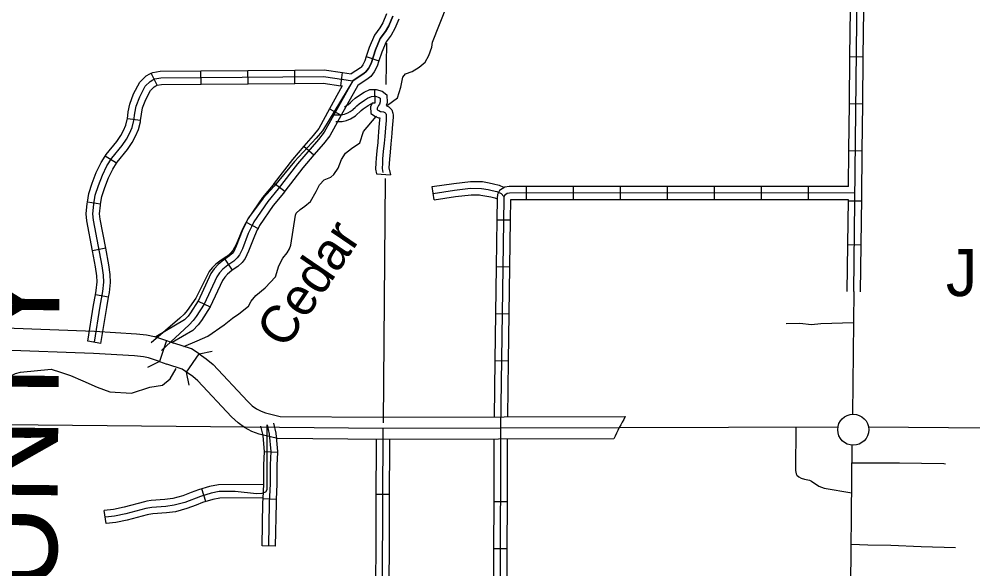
# Model space of a CAD drawing. Extents: x 1373862 to 1376999, y 1168398 to 1170455.
# Drawn here: x 1375582.6 to 1375797.1, y 1168974.9 to 1169098.5 of the extents above; entities that cross this region are included whole.
import ezdxf

# ---------------------------------------------------------------- set-up
doc = ezdxf.new("R2010")
doc.units = 0
for name, color, linetype in [('Level 10', 7, 'Continuous'), ('Level 24', 7, 'Continuous'), ('Level 32', 7, 'Continuous'), ('Level 35', 7, 'Continuous'), ('Level 37', 7, 'Continuous'), ('Level 45', 7, 'Continuous'), ('Level 5', 7, 'Continuous'), ('R_Draft', 7, 'Continuous')]:
    doc.layers.add(name, color=color, linetype=linetype)

msp = doc.modelspace()

# ---------------------------------------------------------------- linework, layer by layer
at = {"layer": 'Level 10'}
for p, q in [((1375615.72, 1169026.21), (1375614.14, 1169021.46)), ((1375620.24, 1169019.11), (1375623.06, 1169023.24))]:
    msp.add_line(p, q, dxfattribs=at)
for points in [[(1375575.37, 1169030.16), (1375578.04, 1169029.33), (1375579.42, 1169029.05), (1375599.53, 1169028.31), (1375608.93, 1169027.73), (1375611.24, 1169027.49), (1375612.98, 1169027.15), (1375615.72, 1169026.21)], [(1375614.14, 1169021.46), (1375611.68, 1169022.31), (1375610.51, 1169022.54), (1375608.53, 1169022.74), (1375599.28, 1169023.32), (1375578.83, 1169024.07), (1375576.8, 1169024.48), (1375573.88, 1169025.39)], [(1375615.72, 1169026.21), (1375617.39, 1169025.63)], [(1375623.06, 1169023.24), (1375621.32, 1169024.31), (1375617.39, 1169025.63)], [(1375623.06, 1169023.24), (1375624.66, 1169022.09), (1375626.18, 1169020.84), (1375633.91, 1169012.58), (1375634.98, 1169011.56), (1375635.92, 1169010.89), (1375636.99, 1169010.3), (1375637.98, 1169009.95), (1375641.3, 1169009.17), (1375664.44, 1169008.95), (1375718.89, 1169009.1)], [(1375614.14, 1169021.46), (1375615.75, 1169020.91)], [(1375620.24, 1169019.11), (1375619.2, 1169019.75), (1375615.75, 1169020.91)], [(1375716.29, 1169004.09), (1375664.43, 1169003.95), (1375640.69, 1169004.17), (1375636.55, 1169005.15), (1375634.93, 1169005.73), (1375633.27, 1169006.65), (1375631.79, 1169007.69), (1375630.36, 1169009.06), (1375622.75, 1169017.18), (1375621.61, 1169018.12), (1375620.24, 1169019.11)], [(1375766.7, 1169006.73), (1375717.51, 1169006.6)], [(1375810.66, 1168942.85), (1375802.81, 1168949.14), (1375798.84, 1168952.2), (1375796.61, 1168953.74), (1375794.39, 1168954.87), (1375775.91, 1168959.64), (1375772.5, 1168960.73), (1375771.74, 1168961.21), (1375770.37, 1168962.36), (1375769.5, 1168963.6), (1375769.9, 1169002.68)]]:
    msp.add_lwpolyline(points, dxfattribs=at)
msp.add_arc((1375767.97, 1168980.4), 56.86, 149.6783, 155.3676, dxfattribs=at)
at = {"layer": 'Level 24'}
msp.add_circle((1375770.15, 1169006.17), 3.5, dxfattribs=at)
at = {"layer": 'Level 32'}
for p, q in [((1375660.64, 1169090.04), (1375663.48, 1169089.09)), ((1375769.4, 1169090.02), (1375772.4, 1169089.98)), ((1375613.6, 1169083.58), (1375612.29, 1169086.28)), ((1375623.48, 1169083.82), (1375623.45, 1169086.82)), ((1375634.04, 1169083.91), (1375634.01, 1169086.91)), ((1375644.6, 1169084.01), (1375644.57, 1169087.01)), ((1375654.89, 1169083.49), (1375655.32, 1169086.46)), ((1375769.28, 1169079.46), (1375772.28, 1169079.42)), ((1375652.37, 1169078.29), (1375655, 1169076.84)), ((1375609.89, 1169075.7), (1375606.92, 1169076.06)), ((1375646.6, 1169069.88), (1375648.87, 1169067.92)), ((1375769.17, 1169068.9), (1375772.17, 1169068.86)), ((1375604.46, 1169066.07), (1375601.92, 1169067.66)), ((1375639.95, 1169061.57), (1375642.34, 1169059.75)), ((1375696.61, 1169060.83), (1375696.61, 1169057.83)), ((1375707.17, 1169060.83), (1375707.17, 1169057.83)), ((1375717.73, 1169060.83), (1375717.73, 1169057.83)), ((1375728.29, 1169060.83), (1375728.29, 1169057.83)), ((1375738.85, 1169060.83), (1375738.85, 1169057.83)), ((1375749.41, 1169060.84), (1375749.41, 1169057.84)), ((1375759.97, 1169060.84), (1375759.97, 1169057.84)), ((1375769.11, 1169057.62), (1375772.11, 1169057.59)), ((1375600.9, 1169056.86), (1375597.93, 1169057.33)), ((1375690, 1169053.37), (1375693, 1169053.33)), ((1375633.65, 1169052.82), (1375636.29, 1169051.41)), ((1375602.04, 1169046.95), (1375599.09, 1169046.39)), ((1375768.93, 1169047.78), (1375771.93, 1169047.75)), ((1375628.84, 1169044.51), (1375630.51, 1169042.02)), ((1375689.85, 1169042.82), (1375692.85, 1169042.77)), ((1375602.69, 1169035.96), (1375599.74, 1169036.5)), ((1375622.84, 1169035.06), (1375625.56, 1169033.8)), ((1375689.7, 1169032.26), (1375692.7, 1169032.21)), ((1375600.98, 1169025.57), (1375598.02, 1169026.05)), ((1375689.55, 1169021.7), (1375692.55, 1169021.66)), ((1375640.76, 1169001.03), (1375637.76, 1169001.21)), ((1375640.45, 1168990.5), (1375637.45, 1168990.63)), ((1375689.3, 1168990), (1375692.3, 1168990)), ((1375640.24, 1168979.98), (1375637.24, 1168980.04)), ((1375689.28, 1168979.44), (1375692.28, 1168979.44))]:
    msp.add_line(p, q, dxfattribs=at)
for points in [[(1375770.29, 1169037.2), (1375771.11, 1169111.53), (1375771.83, 1169217.93)], [(1375769.4, 1169090.02), (1375769.52, 1169100.58)], [(1375772.4, 1169089.98), (1375772.52, 1169100.54)], [(1375666.59, 1169099.11), (1375665.69, 1169096.98), (1375664.93, 1169095.65), (1375663.78, 1169094.08), (1375662.72, 1169091.54), (1375661.7, 1169088.49), (1375661.11, 1169087.36), (1375660.55, 1169086.58), (1375660.19, 1169086.29), (1375657.58, 1169084.61)], [(1375665.19, 1169099.63), (1375664.34, 1169097.64), (1375663.67, 1169096.46), (1375662.47, 1169094.82), (1375661.32, 1169092.07), (1375660.64, 1169090.04)], [(1375667.95, 1169098.46), (1375667.03, 1169096.31), (1375666.2, 1169094.83), (1375665.1, 1169093.33), (1375664.13, 1169091.02), (1375663.48, 1169089.09)], [(1375660.64, 1169090.04), (1375660.32, 1169089.08), (1375659.83, 1169088.15), (1375659.45, 1169087.62), (1375659.32, 1169087.52), (1375657.24, 1169086.18)], [(1375769.28, 1169079.46), (1375769.4, 1169090.02)], [(1375772.28, 1169079.42), (1375772.4, 1169089.98)], [(1375663.48, 1169089.09), (1375663.09, 1169087.9), (1375662.39, 1169086.58), (1375661.65, 1169085.53), (1375661.07, 1169085.07), (1375658.71, 1169083.55)], [(1375599.5, 1169025.81), (1375600.78, 1169033.9), (1375601.4, 1169037.23), (1375601.63, 1169039.34), (1375601.56, 1169040.9), (1375601.26, 1169043), (1375599.3, 1169053.29), (1375599.17, 1169054.71), (1375599.38, 1169056.85), (1375599.7, 1169058.9), (1375600.41, 1169061.07), (1375601.29, 1169063.38), (1375602.32, 1169065.47), (1375603.39, 1169067.18), (1375605.73, 1169070.05), (1375606.72, 1169071.48), (1375607.42, 1169072.76), (1375608.01, 1169074.11), (1375608.38, 1169075.64), (1375608.58, 1169077.34), (1375608.89, 1169078.91), (1375609.68, 1169081.02), (1375610.9, 1169083.35), (1375612.06, 1169084.46), (1375612.66, 1169084.79), (1375613.12, 1169085.01), (1375614.42, 1169085.24), (1375651.05, 1169085.56), (1375657.58, 1169084.61), (1375651.2, 1169073.06), (1375649.87, 1169071.37), (1375645.18, 1169065.94), (1375640.85, 1169060.28), (1375638.47, 1169057.43), (1375635.38, 1169052.88), (1375634.79, 1169051.77), (1375634.1, 1169050.29), (1375632.78, 1169046.85), (1375632.13, 1169045.46), (1375631.61, 1169044.78), (1375630.84, 1169044.05), (1375629.54, 1169043.18), (1375628.38, 1169042.23), (1375627.63, 1169041.4), (1375627, 1169040.49), (1375624.18, 1169034.38), (1375622.37, 1169031.58), (1375621.72, 1169030.71), (1375620.8, 1169029.76), (1375614.55, 1169023.97)], [(1375606.92, 1169076.06), (1375607.1, 1169077.58), (1375607.45, 1169079.32), (1375608.31, 1169081.63), (1375609.69, 1169084.26), (1375611.16, 1169085.68), (1375611.97, 1169086.12), (1375612.29, 1169086.28)], [(1375612.29, 1169086.28), (1375612.65, 1169086.45), (1375614.28, 1169086.74), (1375623.45, 1169086.82)], [(1375623.45, 1169086.82), (1375634.01, 1169086.91)], [(1375634.01, 1169086.91), (1375644.57, 1169087.01)], [(1375644.57, 1169087.01), (1375651.15, 1169087.06), (1375655.32, 1169086.46)], [(1375655.32, 1169086.46), (1375657.24, 1169086.18)], [(1375609.89, 1169075.7), (1375610.07, 1169077.11), (1375610.34, 1169078.5), (1375611.05, 1169080.41), (1375612.12, 1169082.44), (1375612.95, 1169083.24), (1375613.34, 1169083.45), (1375613.6, 1169083.58)], [(1375613.58, 1169083.57), (1375614.55, 1169083.74), (1375623.48, 1169083.82)], [(1375623.48, 1169083.82), (1375634.04, 1169083.91)], [(1375634.04, 1169083.91), (1375644.6, 1169084.01)], [(1375644.6, 1169084.01), (1375650.94, 1169084.06), (1375654.89, 1169083.49)], [(1375654.89, 1169083.49), (1375655.22, 1169083.44), (1375652.37, 1169078.29)], [(1375658.71, 1169083.55), (1375655, 1169076.84)], [(1375769.17, 1169068.9), (1375769.28, 1169079.46)], [(1375772.17, 1169068.86), (1375772.28, 1169079.42)], [(1375652.37, 1169078.29), (1375649.94, 1169073.89), (1375648.71, 1169072.32), (1375646.6, 1169069.88)], [(1375655, 1169076.84), (1375652.45, 1169072.23), (1375651.02, 1169070.41), (1375648.87, 1169067.92)], [(1375601.92, 1169067.66), (1375602.17, 1169068.06), (1375604.53, 1169070.95), (1375605.44, 1169072.26), (1375606.07, 1169073.42), (1375606.58, 1169074.59), (1375606.9, 1169075.91), (1375606.92, 1169076.06)], [(1375604.46, 1169066.07), (1375604.61, 1169066.31), (1375606.93, 1169069.14), (1375608, 1169070.69), (1375608.76, 1169072.11), (1375609.43, 1169073.63), (1375609.85, 1169075.37), (1375609.89, 1169075.7)], [(1375646.6, 1169069.88), (1375644.01, 1169066.89), (1375639.95, 1169061.57)], [(1375769.08, 1169060.84), (1375769.17, 1169068.9)], [(1375772.05, 1169058.31), (1375772.17, 1169068.86)], [(1375597.93, 1169057.33), (1375598.24, 1169059.25), (1375598.99, 1169061.57), (1375599.92, 1169063.98), (1375601.01, 1169066.2), (1375601.92, 1169067.66)], [(1375600.9, 1169056.86), (1375601.17, 1169058.55), (1375601.82, 1169060.57), (1375602.67, 1169062.78), (1375603.63, 1169064.74), (1375604.46, 1169066.07)], [(1375648.87, 1169067.92), (1375646.34, 1169064.99), (1375642.34, 1169059.75)], [(1375639.95, 1169061.57), (1375639.68, 1169061.21), (1375637.27, 1169058.34), (1375634.09, 1169053.66), (1375633.65, 1169052.82)], [(1375642.34, 1169059.75), (1375642.02, 1169059.34), (1375639.67, 1169056.53), (1375636.66, 1169052.1), (1375636.29, 1169051.41)], [(1375696.61, 1169060.83), (1375692.79, 1169060.82), (1375691.77, 1169060.71), (1375690.63, 1169059.9), (1375690.17, 1169059.01), (1375690.07, 1169058.22), (1375690, 1169053.37)], [(1375707.17, 1169060.83), (1375696.61, 1169060.83)], [(1375717.73, 1169060.83), (1375707.17, 1169060.83)], [(1375728.29, 1169060.83), (1375717.73, 1169060.83)], [(1375738.85, 1169060.83), (1375728.29, 1169060.83)], [(1375749.41, 1169060.84), (1375738.85, 1169060.83)], [(1375759.97, 1169060.84), (1375749.41, 1169060.84)], [(1375769.08, 1169060.84), (1375759.97, 1169060.84)], [(1375770.53, 1169059.37), (1375692.88, 1169059.35), (1375692.32, 1169059.29), (1375691.78, 1169058.9), (1375691.6, 1169058.56), (1375691.54, 1169058.12), (1375690.81, 1169006.53), (1375690.58, 1168902.11)], [(1375696.61, 1169057.83), (1375693.07, 1169057.82), (1375693, 1169053.33)], [(1375707.17, 1169057.83), (1375696.61, 1169057.83)], [(1375717.73, 1169057.83), (1375707.17, 1169057.83)], [(1375728.29, 1169057.83), (1375717.73, 1169057.83)], [(1375738.85, 1169057.83), (1375728.29, 1169057.83)], [(1375749.41, 1169057.84), (1375738.85, 1169057.83)], [(1375759.97, 1169057.84), (1375749.41, 1169057.84)], [(1375769.04, 1169057.84), (1375759.97, 1169057.84)], [(1375768.93, 1169047.78), (1375769.04, 1169057.84)], [(1375771.93, 1169047.75), (1375772.05, 1169058.31)], [(1375599.09, 1169046.39), (1375597.82, 1169053.08), (1375597.67, 1169054.71), (1375597.89, 1169057.04), (1375597.93, 1169057.33)], [(1375602.04, 1169046.95), (1375600.79, 1169053.49), (1375600.68, 1169054.7), (1375600.87, 1169056.66), (1375600.9, 1169056.86)], [(1375690, 1169053.37), (1375689.85, 1169042.82)], [(1375693, 1169053.33), (1375692.85, 1169042.77)], [(1375633.65, 1169052.82), (1375633.44, 1169052.44), (1375632.71, 1169050.87), (1375631.4, 1169047.44), (1375630.84, 1169046.24), (1375630.49, 1169045.78), (1375629.9, 1169045.23), (1375628.84, 1169044.51)], [(1375636.29, 1169051.41), (1375636.13, 1169051.1), (1375635.48, 1169049.7), (1375634.16, 1169046.26), (1375633.42, 1169044.68), (1375632.73, 1169043.77), (1375631.77, 1169042.87), (1375630.51, 1169042.02)], [(1375602.69, 1169035.96), (1375602.89, 1169037.01), (1375603.13, 1169039.29), (1375603.05, 1169041.04), (1375602.74, 1169043.25), (1375602.04, 1169046.95)], [(1375768.81, 1169037.24), (1375768.93, 1169047.78)], [(1375771.81, 1169037.12), (1375771.93, 1169047.75)], [(1375599.74, 1169036.5), (1375599.92, 1169037.45), (1375600.12, 1169039.38), (1375600.06, 1169040.76), (1375599.78, 1169042.76), (1375599.09, 1169046.39)], [(1375628.84, 1169044.51), (1375628.64, 1169044.38), (1375627.35, 1169043.32), (1375626.46, 1169042.34), (1375625.69, 1169041.24), (1375622.84, 1169035.06)], [(1375689.85, 1169042.82), (1375689.7, 1169032.26)], [(1375692.85, 1169042.77), (1375692.7, 1169032.21)], [(1375630.51, 1169042.02), (1375630.44, 1169041.97), (1375629.42, 1169041.14), (1375628.8, 1169040.46), (1375628.3, 1169039.74), (1375625.56, 1169033.8)], [(1375598.02, 1169026.05), (1375599.31, 1169034.15), (1375599.74, 1169036.5)], [(1375770.29, 1169037.2), (1375769.98, 1169009.66)], [(1375600.98, 1169025.57), (1375602.26, 1169033.65), (1375602.69, 1169035.96)], [(1375622.86, 1169035.1), (1375621.14, 1169032.44), (1375620.58, 1169031.69), (1375619.75, 1169030.84), (1375613.29, 1169027.05)], [(1375625.53, 1169033.76), (1375623.6, 1169030.72), (1375622.86, 1169029.74), (1375621.63, 1169028.46), (1375617.02, 1169025.76)], [(1375689.7, 1169032.26), (1375689.55, 1169021.7)], [(1375692.7, 1169032.21), (1375692.55, 1169021.66)], [(1375689.55, 1169021.7), (1375689.37, 1169009.02)], [(1375692.55, 1169021.66), (1375692.37, 1169009.03)], [(1375637.76, 1169001.21), (1375637.76, 1169001.23), (1375637.43, 1169004.9), (1375636.93, 1169006.93)], [(1375638.74, 1168980.01), (1375638.91, 1168989.75), (1375639.09, 1168993.99), (1375639.09, 1168998.24), (1375639.27, 1169001.25), (1375638.91, 1169005.15), (1375638.39, 1169007.28)], [(1375640.76, 1169001.03), (1375640.77, 1169001.28), (1375640.4, 1169005.39), (1375639.84, 1169007.64)], [(1375757.27, 1169006.71), (1375757.18, 1168997), (1375757.3, 1168996.26), (1375757.49, 1168995.92), (1375757.89, 1168995.55), (1375758.43, 1168995.25), (1375759.15, 1168995.02), (1375760.3, 1168994.8), (1375760.74, 1168994.61), (1375762.37, 1168993.48), (1375763.59, 1168993.05), (1375769.79, 1168991.97)], [(1375818.55, 1169006.35), (1375773.61, 1169006.71)], [(1375689.33, 1169004.02), (1375689.33, 1169000.56)], [(1375692.33, 1169004.03), (1375692.33, 1169000.56)], [(1375637.45, 1168990.63), (1375637.59, 1168994.02), (1375637.59, 1168998.29), (1375637.76, 1169001.21)], [(1375640.45, 1168990.5), (1375640.59, 1168993.96), (1375640.59, 1168998.2), (1375640.76, 1169001.03)], [(1375689.33, 1169000.56), (1375689.3, 1168990)], [(1375692.33, 1169000.56), (1375692.3, 1168990)], [(1375769.86, 1168998.73), (1375780.58, 1168998.73), (1375785.49, 1168998.66), (1375790.55, 1168998.58), (1375790.91, 1168998.51)], [(1375637.24, 1168980.04), (1375637.41, 1168989.79), (1375637.45, 1168990.63)], [(1375640.24, 1168979.98), (1375640.41, 1168989.7), (1375640.45, 1168990.5)], [(1375689.3, 1168990), (1375689.28, 1168979.44)], [(1375692.3, 1168990), (1375692.28, 1168979.44)], [(1375689.28, 1168979.44), (1375689.26, 1168968.88)], [(1375692.28, 1168979.44), (1375692.26, 1168968.88)]]:
    msp.add_lwpolyline(points, dxfattribs=at)
at = {"layer": 'Level 35'}
for points in [[(1375665.39, 1169079.09), (1375667.68, 1169080.79), (1375668.41, 1169083.16), (1375668.87, 1169085.41), (1375669.47, 1169086.13), (1375670.92, 1169086.7), (1375672.56, 1169087.62), (1375673.85, 1169088.79), (1375674.68, 1169090.3), (1375675.39, 1169092.17), (1375675.54, 1169093.29), (1375680.56, 1169106.04), (1375681.27, 1169106.9), (1375682.8, 1169109.38), (1375683.57, 1169113.1)], [(1375619.61, 1169024.9), (1375622.61, 1169026.11), (1375624.97, 1169027.16), (1375628.69, 1169029.72), (1375630.52, 1169031.25), (1375632.01, 1169032.21), (1375634.14, 1169033.95), (1375634.76, 1169035.08), (1375635.78, 1169036.35), (1375637.89, 1169038.04), (1375640.25, 1169040.49), (1375641, 1169043.02), (1375641.85, 1169044.76), (1375642.85, 1169045.89), (1375643.36, 1169046.8), (1375643.64, 1169047.61), (1375644.7, 1169054.4), (1375644.88, 1169054.85), (1375645.74, 1169055.69), (1375646.83, 1169056.42), (1375648.06, 1169057.47), (1375649.39, 1169059.71), (1375650.15, 1169061.22), (1375651.17, 1169062.31), (1375652.69, 1169062.91), (1375653.36, 1169063.51), (1375654.31, 1169064.94), (1375655.03, 1169066.87), (1375655.95, 1169068.31), (1375657.28, 1169069.39), (1375659.18, 1169070.68), (1375660.04, 1169073.18), (1375662.84, 1169076.57), (1375662.95, 1169076.67)], [(1375576.56, 1169012.93), (1375579.62, 1169017.34), (1375580.26, 1169018.03), (1375581.74, 1169018.8), (1375582.9, 1169019.09), (1375589.8, 1169019.78), (1375591.89, 1169019.1), (1375594.16, 1169018.34), (1375596.9, 1169017.13), (1375600.09, 1169015.76), (1375602.98, 1169014.69), (1375607.84, 1169014.39), (1375611.94, 1169015.76), (1375614.82, 1169016.21), (1375616.5, 1169017.58), (1375617.87, 1169019.95)]]:
    msp.add_lwpolyline(points, dxfattribs=at)
at = {"layer": 'Level 37'}
for points in [[(1375623.06, 1169023.24), (1375626.01, 1169023.79)], [(1375614.14, 1169021.46), (1375611.46, 1169020.12)], [(1375620.8, 1169016.16), (1375620.24, 1169019.11)]]:
    msp.add_lwpolyline(points, dxfattribs=at)
at = {"layer": 'Level 45'}
for p, q in [((1375662.62, 1169079.62), (1375662.56, 1169082.62)), ((1375662.95, 1169063.68), (1375666.06, 1169063.45)), ((1375675.87, 1169057.84), (1375675.44, 1169060.81)), ((1375624.52, 1168990), (1375623.64, 1168992.87)), ((1375662.89, 1168991.71), (1375665.89, 1168991.7)), ((1375602.12, 1168985.07), (1375601.67, 1168988.04))]:
    msp.add_line(p, q, dxfattribs=at)
for points in [[(1375657.58, 1169084.61), (1375660.19, 1169086.29), (1375660.55, 1169086.58), (1375661.11, 1169087.36), (1375661.7, 1169088.49), (1375662.72, 1169091.54), (1375663.78, 1169094.08), (1375664.93, 1169095.65), (1375665.69, 1169096.98), (1375666.59, 1169099.11)], [(1375599.5, 1169025.81), (1375600.78, 1169033.9), (1375601.4, 1169037.23), (1375601.63, 1169039.34), (1375601.56, 1169040.9), (1375601.26, 1169043), (1375599.3, 1169053.29), (1375599.17, 1169054.71), (1375599.38, 1169056.85), (1375599.7, 1169058.9), (1375600.41, 1169061.07), (1375601.29, 1169063.38), (1375602.32, 1169065.47), (1375603.39, 1169067.18), (1375605.73, 1169070.05), (1375606.72, 1169071.48), (1375607.42, 1169072.76), (1375608.01, 1169074.11), (1375608.38, 1169075.64), (1375608.58, 1169077.34), (1375608.89, 1169078.91), (1375609.68, 1169081.02), (1375610.9, 1169083.35), (1375612.06, 1169084.46), (1375612.66, 1169084.79), (1375613.12, 1169085.01), (1375614.42, 1169085.24), (1375651.05, 1169085.56), (1375657.58, 1169084.61)], [(1375657.58, 1169084.61), (1375650.76, 1169073.31), (1375649.36, 1169071.67), (1375644.47, 1169066.43), (1375639.93, 1169060.94), (1375637.44, 1169058.19), (1375634.17, 1169053.76), (1375633.54, 1169052.68), (1375632.79, 1169051.22), (1375631.34, 1169047.83), (1375630.64, 1169046.47), (1375630.1, 1169045.81), (1375629.29, 1169045.11), (1375627.97, 1169044.29), (1375626.78, 1169043.38), (1375625.99, 1169042.58), (1375625.32, 1169041.7), (1375622.27, 1169035.7), (1375620.36, 1169032.97), (1375619.67, 1169032.13), (1375618.72, 1169031.22), (1375612.25, 1169025.67)], [(1375653.34, 1169076.93), (1375655.01, 1169076.91), (1375655.77, 1169077.11), (1375656.46, 1169077.38), (1375657.02, 1169077.71), (1375657.69, 1169078.15), (1375657.67, 1169078.19), (1375658.16, 1169078.6), (1375658.5, 1169078.97), (1375659.05, 1169079.44), (1375660.22, 1169080.26), (1375660.89, 1169080.68), (1375661.8, 1169081.08), (1375662.69, 1169081.1), (1375663.51, 1169080.87), (1375663.75, 1169080.67), (1375663.79, 1169079.85), (1375663.62, 1169079.31), (1375663.37, 1169079), (1375663.07, 1169078.47), (1375663.1, 1169078.09), (1375663.43, 1169077.88), (1375663.81, 1169077.71), (1375663.97, 1169077.69), (1375664.51, 1169077.6), (1375664.8, 1169077.48), (1375665.04, 1169077.23), (1375665.12, 1169077.01), (1375665.13, 1169076.77), (1375665.14, 1169076.43), (1375665.09, 1169075.7), (1375664.94, 1169074.04), (1375664.8, 1169072.05), (1375664.67, 1169070.56), (1375664.46, 1169068.73), (1375664.31, 1169067.08), (1375664.25, 1169066.05), (1375664.21, 1169064.87), (1375664.39, 1169064.01)], [(1375655.75, 1169078.74), (1375656.21, 1169079.01), (1375656.48, 1169079.18), (1375657.1, 1169079.7), (1375657.43, 1169080.06), (1375658.11, 1169080.65), (1375659.37, 1169081.54), (1375660.18, 1169082.04), (1375661.47, 1169082.6), (1375662.56, 1169082.62)], [(1375662.56, 1169082.62), (1375662.88, 1169082.63), (1375664.22, 1169082.26), (1375665.25, 1169081.43), (1375665.33, 1169079.65), (1375665.12, 1169079), (1375665.69, 1169078.77), (1375666.38, 1169078.03), (1375666.63, 1169077.31), (1375666.66, 1169076.83), (1375666.67, 1169076.38), (1375666.61, 1169075.59), (1375666.46, 1169073.91), (1375666.39, 1169072.81)], [(1375653.77, 1169075.45), (1375655.19, 1169075.44), (1375656.22, 1169075.7), (1375657.11, 1169076.06), (1375657.12, 1169076.06), (1375658.25, 1169076.69), (1375659.52, 1169077.91), (1375659.95, 1169078.28), (1375661.03, 1169079.03), (1375661.57, 1169079.37), (1375662.12, 1169079.61), (1375662.62, 1169079.62)], [(1375662.02, 1169079.61), (1375661.58, 1169078.8), (1375661.68, 1169077.26), (1375662.71, 1169076.58), (1375663.42, 1169076.27), (1375663.65, 1169076.24), (1375663.62, 1169075.82), (1375663.47, 1169074.15), (1375663.39, 1169073.02)], [(1375663.39, 1169073.02), (1375663.33, 1169072.16), (1375663.2, 1169070.71), (1375663, 1169068.88), (1375662.84, 1169067.19), (1375662.78, 1169066.12), (1375662.73, 1169064.74), (1375662.95, 1169063.68)], [(1375666.39, 1169072.81), (1375666.32, 1169071.92), (1375666.19, 1169070.4), (1375665.98, 1169068.57), (1375665.83, 1169066.96), (1375665.78, 1169065.98), (1375665.74, 1169065), (1375666.06, 1169063.45)], [(1375675.44, 1169060.81), (1375680.31, 1169061.53), (1375684.04, 1169061.97), (1375686.17, 1169061.93)], [(1375686.17, 1169061.93), (1375686.74, 1169061.92), (1375688.3, 1169061.62), (1375689.25, 1169061.43), (1375690.5, 1169061.15), (1375691.49, 1169060.68)], [(1375675.66, 1169059.29), (1375680.51, 1169060.01), (1375684.11, 1169060.44), (1375686.58, 1169060.39), (1375688.01, 1169060.12), (1375688.93, 1169059.94), (1375690, 1169059.7), (1375690.96, 1169059.24), (1375691.6, 1169058.56)], [(1375675.87, 1169057.84), (1375680.71, 1169058.55), (1375684.19, 1169058.97), (1375686.11, 1169058.93)], [(1375686.11, 1169058.93), (1375686.42, 1169058.92), (1375687.73, 1169058.67), (1375688.63, 1169058.49), (1375689.51, 1169058.3), (1375690.07, 1169058.03)], [(1375755.07, 1169030.01), (1375758.14, 1169030.15), (1375760.78, 1169029.85), (1375762.82, 1169030.07), (1375770.21, 1169030.3)], [(1375638.29, 1169007.26), (1375638.28, 1168992.65), (1375637.96, 1168992.12), (1375637.18, 1168991.84), (1375635.94, 1168991.77), (1375631.13, 1168992.29), (1375627.52, 1168992.28), (1375625.78, 1168991.93), (1375623.36, 1168991.19), (1375619.85, 1168989.84), (1375617.47, 1168989.18), (1375615.53, 1168988.93), (1375612.45, 1168988.7), (1375611.07, 1168988.49), (1375606.53, 1168987.29), (1375604.05, 1168986.75), (1375602.03, 1168986.54)], [(1375690.69, 1168953.19), (1375666.86, 1168953.51), (1375666.4, 1168953.67), (1375665.13, 1168954.44), (1375664.6, 1168955.04), (1375664.18, 1168956.04), (1375664.43, 1169006.45)], [(1375662.94, 1169002.27), (1375662.95, 1169003.97)], [(1375665.94, 1169002.26), (1375665.95, 1169003.96)], [(1375662.89, 1168991.71), (1375662.94, 1169002.27)], [(1375665.89, 1168991.7), (1375665.94, 1169002.26)], [(1375637.58, 1168993.83), (1375627.37, 1168993.81), (1375625.41, 1168993.41), (1375622.87, 1168992.64), (1375621.29, 1168992.03)], [(1375621.29, 1168992.03), (1375619.37, 1168991.29), (1375617.17, 1168990.68), (1375615.37, 1168990.45), (1375612.28, 1168990.22), (1375611.31, 1168990.07)], [(1375662.83, 1168981.15), (1375662.89, 1168991.71)], [(1375665.83, 1168981.14), (1375665.89, 1168991.7)], [(1375611.31, 1168990.07), (1375610.75, 1168989.99), (1375606.17, 1168988.78), (1375603.8, 1168988.26), (1375601.67, 1168988.04)], [(1375622.37, 1168989.23), (1375620.31, 1168988.44), (1375617.76, 1168987.74), (1375615.68, 1168987.46), (1375612.61, 1168987.24), (1375611.77, 1168987.11)], [(1375637.43, 1168990.83), (1375627.67, 1168990.81), (1375626.15, 1168990.5), (1375623.84, 1168989.8), (1375622.37, 1168989.23)], [(1375611.77, 1168987.11), (1375611.37, 1168987.05), (1375606.87, 1168985.86), (1375604.28, 1168985.3), (1375602.12, 1168985.07)], [(1375662.78, 1168970.59), (1375662.83, 1168981.15)], [(1375665.78, 1168970.58), (1375665.83, 1168981.14)], [(1375793.16, 1168979.64), (1375785.44, 1168979.87), (1375778.56, 1168980.11), (1375773.39, 1168980.19), (1375769.68, 1168980.38)]]:
    msp.add_lwpolyline(points, dxfattribs=at)
at = {"layer": 'Level 5'}
for points in [[(1375665.15, 1169093.05), (1375665.07, 1169083.77)], [(1375664.9, 1169062.61), (1375664.45, 1169007.74)], [(1375717.51, 1169006.6), (1375664.43, 1169006.45), (1375563.49, 1169007.39)]]:
    msp.add_lwpolyline(points, dxfattribs=at)

# ---------------------------------------------------------------- texts
at = {"layer": 'Level 24'}
msp.add_text('Jerusalem', height=10.56, dxfattribs=at).set_placement((1375790.97, 1169036.2))
at = {"layer": 'Level 35'}
msp.add_text('Cedar', height=8.44, rotation=55.7471, dxfattribs=at).set_placement((1375642.4, 1169024.03))
at = {"layer": 'R_Draft'}
msp.add_text('CONWAY COUNTY', height=20.2145, rotation=89.4588, dxfattribs=at).set_placement((1375589.41, 1168800.01))

doc.saveas('drawing.dxf')
